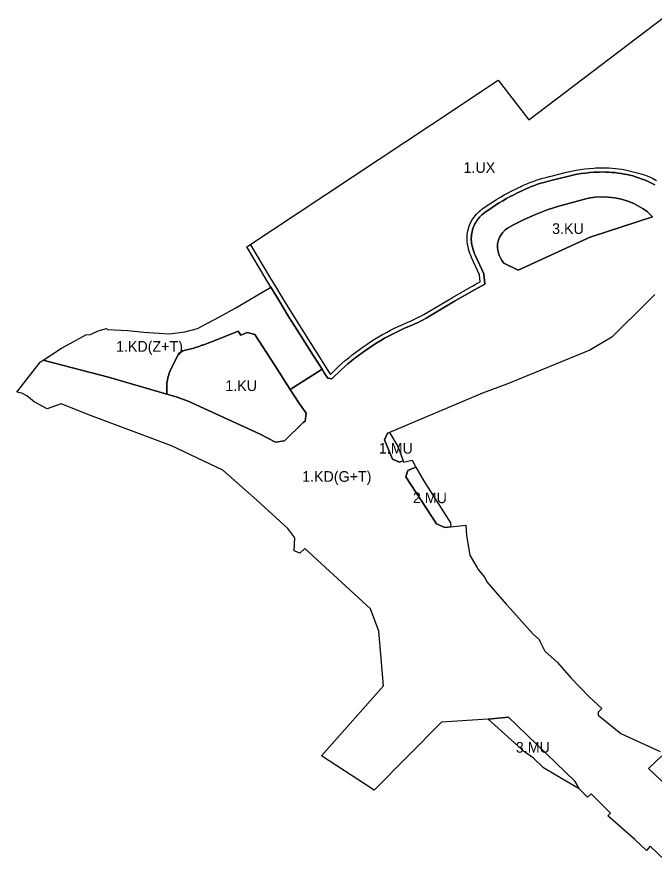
# Model space of a CAD drawing. Extents: x 7426363 to 7427567, y 5543397 to 5546605.
# Drawn here: x 7426457 to 7427055, y 5543397 to 5544188 of the extents above; entities that cross this region are included whole.
import ezdxf

# ---------------------------------------------------------------- set-up
doc = ezdxf.new("R2010")
doc.units = 0
for name, color, linetype in [('linie_rozgraniczajace', 7, 'Continuous'), ('linie_zabudowy_nieprzekraczalne', 7, 'Continuous'), ('oznaczenia_przeznaczen', 7, 'Continuous')]:
    doc.layers.add(name, color=color, linetype=linetype)

msp = doc.modelspace()

# ---------------------------------------------------------------- linework, layer by layer
at = {"layer": 'linie_rozgraniczajace'}
for points in [[(7426672.88, 5543972.3), (7426846.18, 5544087.44), (7426908.85, 5544129.08), (7426937.57, 5544091.78), (7427065.07, 5544188.4)], [(7427055.85, 5544030.73), (7427053.38, 5544032.02), (7427050.88, 5544033.24), (7427048.34, 5544034.39), (7427045.77, 5544035.46), (7427043.16, 5544036.46), (7427040.54, 5544037.38), (7427037.88, 5544038.23), (7427035.21, 5544039), (7427032.51, 5544039.69), (7427029.79, 5544040.31), (7427029.73, 5544040.32), (7427027.34, 5544040.8), (7427024.39, 5544041.31), (7427021.43, 5544041.75), (7427018.46, 5544042.1), (7427015.48, 5544042.38), (7427012.49, 5544042.57), (7427009.5, 5544042.69), (7427006.51, 5544042.73), (7427003.51, 5544042.68), (7427000.52, 5544042.56), (7426998.83, 5544042.45), (7426994.78, 5544042.11), (7426990.74, 5544041.7), (7426986.7, 5544041.21), (7426982.68, 5544040.64), (7426973.8, 5544038.64), (7426958.4, 5544034.67), (7426957.72, 5544034.51), (7426954.73, 5544033.79), (7426951.76, 5544032.99), (7426948.81, 5544032.12), (7426945.88, 5544031.17), (7426942.98, 5544030.14), (7426940.1, 5544029.03), (7426937.26, 5544027.86), (7426934.44, 5544026.61), (7426931.66, 5544025.28), (7426930.51, 5544024.76), (7426926.96, 5544023.1), (7426923.45, 5544021.38), (7426919.98, 5544019.58), (7426916.54, 5544017.71), (7426913.15, 5544015.77), (7426909.79, 5544013.76), (7426906.47, 5544011.68), (7426903.2, 5544009.53), (7426899.98, 5544007.32), (7426896.79, 5544005.05), (7426896, 5544004.48), (7426894.77, 5544003.54), (7426893.59, 5544002.54), (7426892.46, 5544001.47), (7426891.39, 5544000.35), (7426890.38, 5543999.18), (7426889.44, 5543997.95), (7426888.55, 5543996.68), (7426887.74, 5543995.36), (7426886.99, 5543994.01), (7426886.31, 5543992.61), (7426885.71, 5543991.19), (7426885.18, 5543989.73), (7426884.73, 5543988.25), (7426884.35, 5543986.75), (7426884.05, 5543985.23), (7426883.83, 5543983.69), (7426883.69, 5543982.15), (7426883.63, 5543980.6), (7426883.65, 5543979.05), (7426883.75, 5543977.51), (7426883.93, 5543975.97), (7426884.19, 5543974.44)], [(7426948.81, 5544032.12), (7426951.76, 5544032.99), (7426954.73, 5544033.79), (7426957.72, 5544034.51), (7426958.4, 5544034.67), (7426973.8, 5544038.64), (7426982.68, 5544040.64), (7426986.7, 5544041.21), (7426990.74, 5544041.7), (7426994.78, 5544042.11), (7426998.83, 5544042.45), (7427000.52, 5544042.56), (7427003.51, 5544042.68), (7427006.51, 5544042.73), (7427009.5, 5544042.69), (7427012.49, 5544042.57), (7427015.48, 5544042.38), (7427018.46, 5544042.1), (7427021.43, 5544041.75), (7427024.39, 5544041.31), (7427027.34, 5544040.8), (7427029.73, 5544040.32), (7427029.79, 5544040.31), (7427032.51, 5544039.69), (7427035.21, 5544039), (7427037.88, 5544038.23), (7427040.54, 5544037.38), (7427043.16, 5544036.46), (7427045.77, 5544035.46), (7427048.34, 5544034.39), (7427050.88, 5544033.24), (7427053.38, 5544032.02), (7427055.85, 5544030.73)], [(7426457.05, 5543835.93), (7426478.93, 5543864.1), (7426481.63, 5543865.9), (7426492.42, 5543863.08), (7426543.04, 5543849.93), (7426597.82, 5543834.12), (7426606.57, 5543831.49), (7426617.98, 5543827.44), (7426685.42, 5543796.49), (7426699.95, 5543788.88), (7426708.21, 5543790.25), (7426725.83, 5543807.39), (7426727.61, 5543808.84), (7426728.55, 5543816.26), (7426721.58, 5543826.03), (7426713.62, 5543838.46), (7426743.5, 5543857.6), (7426745.64, 5543854.21), (7426748.99, 5543848.97), (7426752.85, 5543848.52), (7426755.5, 5543851.19), (7426758.51, 5543854.12), (7426761.57, 5543856.99), (7426764.69, 5543859.8), (7426767.87, 5543862.56), (7426771.09, 5543865.25), (7426774.37, 5543867.88), (7426777.69, 5543870.44), (7426781.06, 5543872.94), (7426784.48, 5543875.38), (7426787.95, 5543877.75), (7426791.46, 5543880.06), (7426795.01, 5543882.3), (7426798.61, 5543884.47), (7426802.24, 5543886.57), (7426805.92, 5543888.6), (7426809.63, 5543890.56), (7426813.38, 5543892.46), (7426817.17, 5543894.27), (7426820.99, 5543896.02), (7426824.84, 5543897.69), (7426828.72, 5543899.29), (7426831.2, 5543900.33), (7426833.64, 5543901.44), (7426836.05, 5543902.62), (7426838.42, 5543903.87), (7426840.76, 5543905.19), (7426841.16, 5543905.43), (7426868, 5543921.35), (7426886.55, 5543932.15), (7426890.05, 5543934.09), (7426896.28, 5543937.48), (7426895.31, 5543947.12), (7426887.51, 5543964.14), (7426886.75, 5543965.9), (7426886.06, 5543967.69), (7426885.45, 5543969.51), (7426884.91, 5543971.35), (7426884.45, 5543973.21), (7426884.19, 5543974.44), (7426883.93, 5543975.97), (7426883.75, 5543977.51), (7426883.65, 5543979.05), (7426883.63, 5543980.6), (7426883.69, 5543982.15), (7426883.83, 5543983.69), (7426884.05, 5543985.23), (7426884.35, 5543986.75), (7426884.73, 5543988.25), (7426885.18, 5543989.73), (7426885.71, 5543991.19), (7426886.31, 5543992.61), (7426886.99, 5543994.01), (7426887.74, 5543995.36), (7426888.55, 5543996.68), (7426889.44, 5543997.95), (7426890.38, 5543999.18), (7426891.39, 5544000.35), (7426892.46, 5544001.47), (7426893.59, 5544002.54), (7426894.77, 5544003.54), (7426896, 5544004.48), (7426896.79, 5544005.05), (7426899.98, 5544007.32), (7426903.2, 5544009.53), (7426906.47, 5544011.68), (7426909.79, 5544013.76), (7426913.15, 5544015.77), (7426916.54, 5544017.71), (7426919.98, 5544019.58), (7426923.45, 5544021.38), (7426926.96, 5544023.1), (7426930.51, 5544024.76), (7426931.66, 5544025.28), (7426934.44, 5544026.61), (7426937.26, 5544027.86), (7426940.1, 5544029.03), (7426942.98, 5544030.14), (7426945.88, 5544031.17), (7426948.81, 5544032.12)], [(7426884.19, 5543974.44), (7426884.45, 5543973.21), (7426884.91, 5543971.35), (7426885.45, 5543969.51), (7426886.06, 5543967.69), (7426886.75, 5543965.9), (7426887.51, 5543964.14), (7426895.31, 5543947.12), (7426896.28, 5543937.48), (7426890.05, 5543934.09), (7426886.55, 5543932.15), (7426868, 5543921.35), (7426841.16, 5543905.43), (7426840.76, 5543905.19), (7426838.42, 5543903.87), (7426836.05, 5543902.62), (7426833.64, 5543901.44), (7426831.2, 5543900.33), (7426828.72, 5543899.29), (7426824.84, 5543897.69), (7426820.99, 5543896.02), (7426817.17, 5543894.27), (7426813.38, 5543892.46), (7426809.63, 5543890.56), (7426805.92, 5543888.6), (7426802.24, 5543886.57), (7426798.61, 5543884.47), (7426795.01, 5543882.3), (7426791.46, 5543880.06), (7426787.95, 5543877.75), (7426784.48, 5543875.38), (7426781.06, 5543872.94), (7426777.69, 5543870.44), (7426774.37, 5543867.88), (7426771.09, 5543865.25), (7426767.87, 5543862.56), (7426764.69, 5543859.8), (7426761.57, 5543856.99), (7426758.51, 5543854.12), (7426755.5, 5543851.19), (7426752.85, 5543848.52), (7426748.99, 5543848.97), (7426745.64, 5543854.21), (7426743.5, 5543857.6), (7426735.55, 5543870.2), (7426727.42, 5543882.98), (7426717.76, 5543898.16), (7426712.13, 5543907.02), (7426702.97, 5543922.25), (7426695.51, 5543934.67), (7426690.89, 5543942.36), (7426672.88, 5543972.3)], [(7427055.86, 5543927.77), (7427049.2, 5543921.17), (7427015.6, 5543887.53), (7426994.8, 5543875.35), (7426916.98, 5543843.5), (7426894, 5543834.92), (7426806.97, 5543798.25), (7426805.06, 5543797.52), (7426802.28, 5543791.11), (7426809.65, 5543773.03), (7426816.18, 5543770.25), (7426819.65, 5543771.64), (7426820.12, 5543770.4), (7426828, 5543772.08), (7426831.66, 5543765.66), (7426823.92, 5543762.57), (7426822.02, 5543756.54), (7426851.07, 5543712.42), (7426858.79, 5543708.75), (7426864.53, 5543709.57), (7426878.46, 5543711.03), (7426879.21, 5543701.35), (7426882.13, 5543682.91), (7426889.15, 5543670.87), (7426889.87, 5543669.63), (7426896.23, 5543661.8), (7426898.33, 5543658), (7426916.34, 5543636.84), (7426920.35, 5543632.42), (7426941.48, 5543609.11), (7426947.35, 5543603.68), (7426948.2, 5543601.42), (7426952.59, 5543592.72), (7426964.67, 5543582.09)], [(7427065.29, 5543396.54), (7427051.65, 5543409.65), (7427048.1, 5543405.64), (7427037.09, 5543415.94), (7427011.87, 5543438.26), (7427014.33, 5543440.54), (7426996.01, 5543458.78), (7426992.85, 5543455.73), (7426985.02, 5543463.54), (7426980.7, 5543470.6), (7426918.54, 5543530.81), (7426899.35, 5543528.97), (7426894.36, 5543528.63), (7426855.65, 5543525.98), (7426792.5, 5543462.34), (7426743.14, 5543494.33), (7426801.19, 5543560.3), (7426796.71, 5543611.48), (7426788.93, 5543632.67), (7426727.34, 5543689.21), (7426722.6, 5543684.64), (7426717.35, 5543686.86), (7426717.89, 5543699.12), (7426711.46, 5543708.11), (7426682.45, 5543734.65), (7426650.33, 5543762.66), (7426602.29, 5543785.69), (7426526.01, 5543814.22), (7426498.57, 5543825), (7426485.51, 5543820.43), (7426473.18, 5543827.02), (7426466.51, 5543832.49), (7426461.85, 5543835.06), (7426457.05, 5543835.93)], [(7426964.67, 5543582.09), (7426977.38, 5543567.57), (7426994.21, 5543549.88), (7427006.01, 5543539.04), (7427002.64, 5543535.61), (7427002.86, 5543532.76), (7427023.98, 5543515.31), (7427035.6, 5543510.17), (7427061.03, 5543498.44)], [(7427062.6, 5543494.63), (7427049.91, 5543482.52), (7427072.09, 5543461.55)]]:
    msp.add_lwpolyline(points, dxfattribs=at)
for points in [[(7426908.13, 5543971.42), (7426908.72, 5543967.79), (7426909.89, 5543964.5), (7426911, 5543962.08), (7426912.41, 5543959.51), (7426914.18, 5543957.18), (7426927.63, 5543950.47), (7426995.91, 5543981.87), (7426996.13, 5543981.96), (7427053.64, 5544000.58), (7427050.41, 5544004.04), (7427049.57, 5544004.82), (7427048.7, 5544005.56), (7427047.8, 5544006.26), (7427046.88, 5544006.94), (7427045.93, 5544007.58), (7427044.95, 5544008.18), (7427036.07, 5544013.2), (7427030.41, 5544015.48), (7427024.5, 5544017.27), (7427018.4, 5544018.53), (7427012.19, 5544019.24), (7427005.94, 5544019.39), (7426999.73, 5544018.98), (7426993.63, 5544018.02), (7426987.71, 5544016.54), (7426965.87, 5544010.49), (7426954.72, 5544007.04), (7426943.78, 5544002.92), (7426933.1, 5543998.15), (7426922.75, 5543992.76), (7426918.32, 5543990.28), (7426915.43, 5543988.32), (7426912.8, 5543985.74), (7426910.63, 5543982.6), (7426909.06, 5543979.04), (7426908.22, 5543975.24)], [(7426908.13, 5543971.42), (7426908.22, 5543975.24), (7426909.06, 5543979.04), (7426910.63, 5543982.6), (7426912.8, 5543985.74), (7426915.43, 5543988.32), (7426918.32, 5543990.28), (7426922.75, 5543992.76), (7426933.1, 5543998.15), (7426943.78, 5544002.92), (7426954.72, 5544007.04), (7426965.87, 5544010.49), (7426987.71, 5544016.54), (7426993.63, 5544018.02), (7426999.73, 5544018.98), (7427005.94, 5544019.39), (7427012.19, 5544019.24), (7427018.4, 5544018.53), (7427024.5, 5544017.27), (7427030.41, 5544015.48), (7427036.07, 5544013.2), (7427044.95, 5544008.18), (7427045.93, 5544007.58), (7427046.88, 5544006.94), (7427047.8, 5544006.26), (7427048.7, 5544005.56), (7427049.57, 5544004.82), (7427050.41, 5544004.04), (7427053.64, 5544000.58), (7426996.13, 5543981.96), (7426995.91, 5543981.87), (7426927.63, 5543950.47), (7426914.18, 5543957.18), (7426912.41, 5543959.51), (7426911, 5543962.08), (7426909.89, 5543964.5), (7426908.72, 5543967.79)], [(7426481.63, 5543865.9), (7426488.91, 5543870.78), (7426498.9, 5543877.45), (7426507.15, 5543881.66), (7426521.71, 5543889.91), (7426526.22, 5543889.99), (7426529.22, 5543891.79), (7426531.36, 5543892.76), (7426533.5, 5543893.72), (7426541.28, 5543895.9), (7426542.06, 5543894.94), (7426561.08, 5543893.93), (7426576.15, 5543892.24), (7426600.16, 5543890.73), (7426614.63, 5543892.53), (7426626.55, 5543895.62), (7426647.22, 5543906.69), (7426662.64, 5543915.06), (7426695.51, 5543934.67), (7426702.97, 5543922.25), (7426712.13, 5543907.02), (7426717.76, 5543898.16), (7426727.42, 5543882.98), (7426735.55, 5543870.2), (7426743.5, 5543857.6), (7426713.62, 5543838.46), (7426698.77, 5543861.66), (7426680.51, 5543890.17), (7426673.18, 5543892.15), (7426668.99, 5543890.1), (7426667.34, 5543889.6), (7426664.9, 5543893.21), (7426664.82, 5543893.27), (7426642.26, 5543884.09), (7426631.48, 5543880.24), (7426630.79, 5543879.96), (7426628.29, 5543879.01), (7426625.75, 5543878.13), (7426623.19, 5543877.33), (7426620.61, 5543876.6), (7426618, 5543875.95), (7426615.38, 5543875.38), (7426612.86, 5543874.91), (7426608.87, 5543871.95), (7426600.78, 5543855.35), (7426600.14, 5543853.85), (7426599.58, 5543852.33), (7426599.09, 5543850.78), (7426598.68, 5543849.21), (7426598.35, 5543847.62), (7426598.09, 5543846.01), (7426597.92, 5543844.4), (7426597.82, 5543842.78), (7426597.8, 5543841.55), (7426597.82, 5543834.12), (7426543.04, 5543849.93), (7426492.42, 5543863.08)], [(7426597.82, 5543834.12), (7426597.8, 5543841.55), (7426597.82, 5543842.78), (7426597.92, 5543844.4), (7426598.09, 5543846.01), (7426598.35, 5543847.62), (7426598.68, 5543849.21), (7426599.09, 5543850.78), (7426599.58, 5543852.33), (7426600.14, 5543853.85), (7426600.78, 5543855.35), (7426608.87, 5543871.95), (7426612.86, 5543874.91), (7426615.38, 5543875.38), (7426618, 5543875.95), (7426620.61, 5543876.6), (7426623.19, 5543877.33), (7426625.75, 5543878.13), (7426628.29, 5543879.01), (7426630.79, 5543879.96), (7426631.48, 5543880.24), (7426642.26, 5543884.09), (7426664.82, 5543893.27), (7426664.9, 5543893.21), (7426667.34, 5543889.6), (7426668.99, 5543890.1), (7426673.18, 5543892.15), (7426680.51, 5543890.17), (7426698.77, 5543861.66), (7426713.62, 5543838.46), (7426721.58, 5543826.03), (7426728.55, 5543816.26), (7426727.61, 5543808.84), (7426725.83, 5543807.39), (7426708.21, 5543790.25), (7426699.95, 5543788.88), (7426685.42, 5543796.49), (7426617.98, 5543827.44), (7426606.57, 5543831.49)], [(7426802.28, 5543791.11), (7426805.06, 5543797.52), (7426806.97, 5543798.25), (7426814.65, 5543784.88), (7426819.65, 5543771.64), (7426816.18, 5543770.25), (7426809.65, 5543773.03)], [(7426822.02, 5543756.54), (7426823.92, 5543762.57), (7426831.66, 5543765.66), (7426839.42, 5543752.02), (7426864.08, 5543713.43), (7426864.53, 5543709.57), (7426858.79, 5543708.75), (7426851.07, 5543712.42)], [(7426899.35, 5543528.97), (7426918.54, 5543530.81), (7426980.7, 5543470.6), (7426985.02, 5543463.54), (7426969.98, 5543472.32), (7426951.31, 5543483.24), (7426942, 5543492.31), (7426933.42, 5543498.24)]]:
    msp.add_lwpolyline(points, close=True, dxfattribs=at)
at = {"layer": 'linie_zabudowy_nieprzekraczalne'}
for points in [[(7426676.38, 5543974.23), (7426694.31, 5543944.42), (7426698.94, 5543936.73), (7426707.44, 5543922.58), (7426715.35, 5543909.4), (7426730.79, 5543885.13), (7426738.93, 5543872.34), (7426749.01, 5543856.36), (7426751.34, 5543852.72), (7426755.75, 5543857.02), (7426758.87, 5543859.94), (7426762.04, 5543862.8), (7426765.27, 5543865.6), (7426768.56, 5543868.34), (7426771.89, 5543871.02), (7426775.28, 5543873.63), (7426778.71, 5543876.18), (7426782.19, 5543878.66), (7426785.72, 5543881.08), (7426789.3, 5543883.42), (7426792.91, 5543885.7), (7426796.57, 5543887.91), (7426800.28, 5543890.05), (7426804.02, 5543892.12), (7426807.8, 5543894.12), (7426811.62, 5543896.04), (7426815.47, 5543897.9), (7426819.36, 5543899.67), (7426823.28, 5543901.38), (7426827.2, 5543902.99), (7426839.12, 5543908.87), (7426865.97, 5543924.8), (7426884.54, 5543935.61), (7426884.61, 5543935.65), (7426888.12, 5543937.6), (7426892.03, 5543939.73), (7426891.39, 5543946.06), (7426883.88, 5543962.47), (7426883.84, 5543962.55), (7426883.05, 5543964.39), (7426882.3, 5543966.33), (7426881.63, 5543968.31), (7426881.05, 5543970.31), (7426880.55, 5543972.32), (7426880.28, 5543973.62), (7426880.25, 5543973.78), (7426879.97, 5543975.4), (7426879.77, 5543977.15), (7426879.65, 5543978.9), (7426879.63, 5543980.65), (7426879.7, 5543982.41), (7426879.86, 5543984.16), (7426880.11, 5543985.9), (7426880.44, 5543987.62), (7426880.87, 5543989.32), (7426881.39, 5543991), (7426881.99, 5543992.65), (7426882.67, 5543994.27), (7426883.44, 5543995.85), (7426884.28, 5543997.38), (7426885.21, 5543998.88), (7426886.21, 5544000.32), (7426887.28, 5544001.71), (7426888.43, 5544003.04), (7426889.64, 5544004.31), (7426890.91, 5544005.52), (7426892.25, 5544006.65), (7426893.63, 5544007.71), (7426894.48, 5544008.31), (7426897.68, 5544010.6), (7426900.98, 5544012.86), (7426904.32, 5544015.05), (7426907.7, 5544017.17), (7426911.13, 5544019.22), (7426914.6, 5544021.2), (7426918.1, 5544023.11), (7426921.65, 5544024.95), (7426925.23, 5544026.71), (7426928.84, 5544028.4), (7426930.02, 5544028.93), (7426929.94, 5544028.89), (7426932.77, 5544030.24), (7426935.68, 5544031.53), (7426938.62, 5544032.75), (7426941.59, 5544033.89), (7426944.59, 5544034.95), (7426947.62, 5544035.94), (7426950.67, 5544036.84), (7426953.74, 5544037.67), (7426956.82, 5544038.41), (7426957.46, 5544038.55), (7426972.86, 5544042.53), (7426981.96, 5544044.58), (7426986.18, 5544045.18), (7426990.3, 5544045.68), (7426994.42, 5544046.1), (7426998.54, 5544046.43)], [(7426998.54, 5544046.43), (7427000.3, 5544046.55), (7427003.4, 5544046.68), (7427006.5, 5544046.73), (7427009.6, 5544046.69), (7427012.7, 5544046.57), (7427015.79, 5544046.36), (7427018.88, 5544046.08), (7427021.96, 5544045.71), (7427025.02, 5544045.26), (7427028.07, 5544044.73), (7427030.51, 5544044.24), (7427040.71, 5544041.76), (7427047.05, 5544039.68), (7427053.68, 5544036.81), (7427057.52, 5544034.74)]]:
    msp.add_lwpolyline(points, dxfattribs=at)

# ---------------------------------------------------------------- texts
at = {"layer": 'oznaczenia_przeznaczen'}
for s, p in [('1.UX', (7426876.34, 5544041.94)), ('3.KU', (7426959.49, 5543984.56)), ('1.KD(Z+T)', (7426550.17, 5543873.96)), ('1.KU', (7426652.72, 5543837.08)), ('1.MU', (7426796.8, 5543778.26)), ('1.KD(G+T)', (7426724.85, 5543751.82)), ('2.MU', (7426828.8, 5543731.75)), ('3.MU', (7426925.43, 5543497.42))]:
    msp.add_text(s, height=10, dxfattribs=at).set_placement(p)

doc.saveas('drawing.dxf')
